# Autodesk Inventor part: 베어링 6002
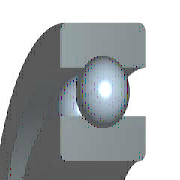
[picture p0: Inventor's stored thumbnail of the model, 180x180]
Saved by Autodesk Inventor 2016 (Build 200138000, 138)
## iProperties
Created: 2012-02
Part Number: 베어링 6002
Material: 강철, 연강
Description: 깊은 그루브 볼 베어링
Document SubType Name: Modeling
Standard: KS B 2023
Designer: mduedu
Standards Organization: KS
Language: ko-KR
Size Designation: 6002 - 15 x 32 x 9
Categories: <MemberInstance><Categories><Category DisplayName="샤프트 부품" InternalName="7f7aeb1f-a693-4053-b835-cee3144e0d98" Mnemonic="SHFT"><Category DisplayName="베어링" Inter
Density: 1 g/cm^3
Appearance: 노란색
IsCustomPart: 0
Author: mduedu
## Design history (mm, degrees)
sketch "스케치" dims "d0" = 4.42 (= -0.26 x WD + 0.26 x BD)
  geometry: L1 (2.29, 11.75)-(6.71, 11.75); L2 (4.5, 11.75)-(4.5, 9.54); L3 (4.5, 11.75)-(4.5, 13.96); L4 (2.858, 10.271)-(0, 10.271); L5 (0, 7.5)-(9, 7.5); L6 (2.858, 13.229)-(0, 13.229); L7 (0, 16)-(9, 16); L8 (9, 7.5)-(9, 10.271); L9 (6.142, 10.271)-(9, 10.271); L10 (6.142, 13.229)-(9, 13.229); L11 (9, 16)-(9, 13.229); L12 (-1.4, 0)-(8.4, 0) reference; L13 (0, -0.3)-(0, 5.3) reference
  constraints: 22 end point, 4 point on line, 2 collinear, 2 perpendicular, 2 symmetric about line, 1 midpoint, 1 parallel, 14 other
  dimensions: "d9" = 15 diameter of L5 L12 (= WD); "d11" = 32 diameter of L7 L12 (= BD); "d12" = 9 distance between parallel lines of L8 L13 (= KB); "d13" = 20.542 diameter of L9 L12 (= 0.326 x BD + 0.674 x WD)
revolve "본체" stored, may be unused: angle "d6" = 90 deg
revolve "볼" stored, may be unused: angle "d7" = 90 deg
pattern_circular "IDS_ARRAYBALL[SIMPL:T]" dims angle "d3" = 360 deg
body "Solid1"
fillet "모깎기1" dims "d1" = 0.3 (= KRS)
other parameters: "WD" = 15 [user parameter; used in 5 equation terms], "BD" = 32 [user parameter; used in 5 equation terms], "KB" = 9 [user parameter; used in 1 equation term], "KRS" = 0.3 [user parameter; used in 1 equation term], "d4" = 0, "d5" = 0, "d8" = 0, "d14" = 0, "d15" = 0, "BBA" = 0 [user parameter], "BC0" = 2850000 [user parameter], "BC" = 5590000 [user parameter], "BR" = 16 (= 0.5 x BD) [user parameter], "WR" = 7.5 (= 0.5 x WD) [user parameter]
